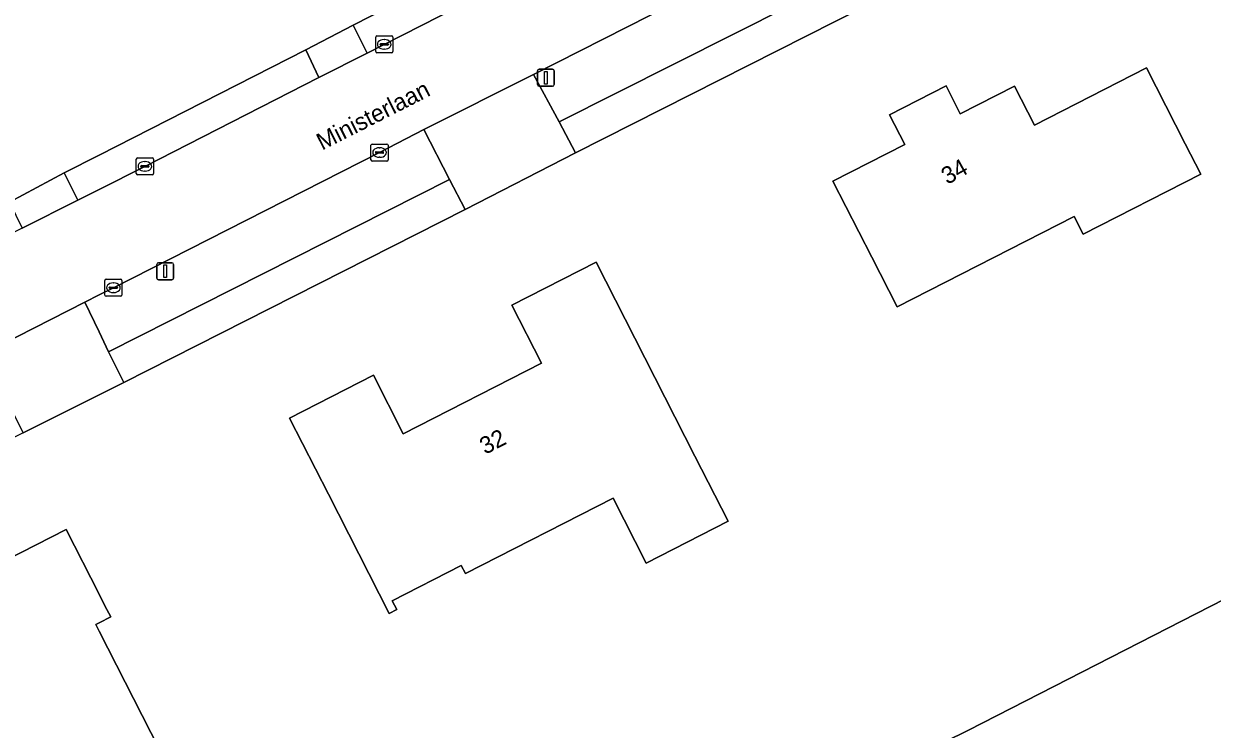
# Model space of a CAD drawing. Extents: x 162722 to 165104, y 384719 to 386284.
# Drawn here: x 163995.6 to 164065.3, y 384949.8 to 384991.2 of the extents above; entities that cross this region are included whole.
import ezdxf

# ---------------------------------------------------------------- set-up
doc = ezdxf.new("R2010")
doc.units = 0
for name, color, linetype in [('IMGEO_Erf', 7, 'Continuous'), ('IMGEO_Groenvoorziening', 7, 'Continuous'), ('IMGEO_Kolk', 7, 'Continuous'), ('IMGEO_Lichtmast', 7, 'Continuous'), ('IMGEO_Openbare_ruimte_label', 7, 'Continuous'), ('IMGEO_Pand', 7, 'Continuous'), ('IMGEO_Pand_nummerreeks', 7, 'Continuous'), ('IMGEO_Parkeervlak_open', 7, 'Continuous'), ('IMGEO_Rijbaan_lokaal_open', 7, 'Continuous'), ('IMGEO_Voetpad_open', 7, 'Continuous')]:
    doc.layers.add(name, color=color, linetype=linetype)

msp = doc.modelspace()

# ---------------------------------------------------------------- linework, layer by layer
at = {"layer": 'IMGEO_Erf'}
for points in [[(164105.943, 385023.18), (164100.563, 385020.442), (164096.277, 385018.243), (164085.388, 385012.719), (164080.225, 385010.11), (164060.269, 385000), (164056.001, 384997.838), (164051.623, 384995.596), (164027.937, 384983.596), (164021.461, 384980.283), (164001.447, 384970.146), (164000, 384969.419), (163995.555, 384967.187), (163991.381, 384965.08), (163982.898, 384961.628)], [(164162.179, 385013.171), (164145.217, 385006.018), (164139.932, 385003.079), (164135.488, 385001.967), (164135.303, 385000), (164134.643, 384992.974), (164080.212, 384964.716), (164050.974, 384949.76), (164021.235, 384935.114), (164000, 384925.382), (163995.382, 384923.265), (163988.039, 384927.89), (163958.544, 384912.864), (163932.377, 384900.522), (163925.711, 384900.92), (163897.985, 384886.845), (163900.677, 384881.543), (163922.602, 384892.673)], [(163986.006, 384976.275), (163994.739, 384980.712), (163997.946, 384982.427), (164000, 384983.471), (164012.117, 384989.629), (164014.89, 384991.078), (164032.397, 385000), (164033.264, 385000.442)], [(163995.382, 384923.265), (164000, 384925.382), (164021.235, 384935.114), (164050.974, 384949.76), (164080.212, 384964.716)]]:
    msp.add_lwpolyline(points, dxfattribs=at)
for points in [[(164045.304, 384977.479), (164043.032, 384981.932), (164047.241, 384984.08), (164046.348, 384985.83), (164049.665, 384987.522), (164050.499, 384985.888), (164053.685, 384987.513), (164054.85, 384985.23), (164061.417, 384988.582), (164063.689, 384984.129), (164064.6, 384982.344), (164057.712, 384978.829), (164057.181, 384979.87), (164046.79, 384974.567)], [(164011.175, 384968.055), (164016.089, 384970.562), (164017.84, 384967.13), (164025.939, 384971.263), (164024.203, 384974.665), (164029.144, 384977.187), (164031.417, 384972.734), (164034.939, 384965.832), (164036.891, 384962.008), (164032.082, 384959.553), (164030.14, 384963.358), (164021.48, 384958.939), (164021.239, 384959.412), (164017.189, 384957.345), (164017.452, 384956.831), (164017.016, 384956.609), (164013.448, 384963.602)], [(163983.545, 384951.385), (163992.966, 384956.185), (163991.861, 384958.354), (163998.073, 384961.519), (164000, 384957.739), (164000.347, 384957.058), (164000.684, 384956.398), (164000, 384956.048), (163999.809, 384955.95), (164000, 384955.576), (164003.541, 384948.634), (164000, 384946.829), (163997.388, 384945.497), (163996.23, 384947.769), (163987.622, 384943.383), (163985.815, 384946.93)]]:
    msp.add_lwpolyline(points, close=True, dxfattribs=at)
at = {"layer": 'IMGEO_Groenvoorziening'}
for points in [[(164026.982, 384985.419), (164050.725, 384997.366), (164049.366, 385000), (164049.239, 385000.247), (164048.752, 385000), (164025.477, 384988.187)], [(164000.553, 384971.928), (164020.558, 384982.045), (164019.048, 384984.967), (164016.445, 384983.616), (164000.843, 384975.693), (164000, 384975.271), (163999.171, 384974.857), (164000, 384973.1)]]:
    msp.add_lwpolyline(points, close=True, dxfattribs=at)
at = {"layer": 'IMGEO_Kolk'}
for p, q in [((164016.221, 384989.53), (164016.221, 384990.382)), ((164016.296, 384990.456), (164017.148, 384990.456)), ((164017.222, 384990.382), (164017.222, 384989.53)), ((164016.48, 384989.95), (164016.48, 384989.962)), ((164016.918, 384989.913), (164016.52, 384989.913)), ((164016.523, 384989.999), (164016.921, 384989.999)), ((164016.732, 384989.676), (164016.707, 384989.676)), ((164016.709, 384990.236), (164016.734, 384990.236)), ((164016.964, 384989.962), (164016.964, 384989.95)), ((164017.148, 384989.456), (164016.296, 384989.456)), ((164016.019, 384984.116), (164016.871, 384984.116)), ((164015.944, 384983.19), (164015.944, 384984.042)), ((164016.203, 384983.61), (164016.203, 384983.622)), ((164016.641, 384983.573), (164016.243, 384983.573)), ((164016.246, 384983.659), (164016.644, 384983.659)), ((164016.432, 384983.896), (164016.457, 384983.896)), ((164016.687, 384983.622), (164016.687, 384983.61)), ((164016.945, 384984.042), (164016.945, 384983.19)), ((164002.184, 384982.38), (164002.184, 384983.232)), ((164002.259, 384983.306), (164003.111, 384983.306)), ((164002.443, 384982.8), (164002.443, 384982.812)), ((164002.881, 384982.763), (164002.483, 384982.763)), ((164002.486, 384982.849), (164002.884, 384982.849)), ((164002.672, 384983.086), (164002.697, 384983.086)), ((164002.927, 384982.812), (164002.927, 384982.8)), ((164003.185, 384983.232), (164003.185, 384982.38)), ((164016.871, 384983.116), (164016.019, 384983.116)), ((164016.455, 384983.336), (164016.43, 384983.336)), ((164003.111, 384982.306), (164002.259, 384982.306)), ((164002.695, 384982.526), (164002.67, 384982.526)), ((164000.342, 384975.267), (164000.342, 384976.119)), ((164000.417, 384976.193), (164001.269, 384976.193)), ((164000.601, 384975.687), (164000.601, 384975.699)), ((164000.644, 384975.736), (164001.042, 384975.736)), ((164000.83, 384975.973), (164000.855, 384975.973)), ((164001.085, 384975.699), (164001.085, 384975.687)), ((164001.343, 384976.119), (164001.343, 384975.267)), ((164001.269, 384975.193), (164000.417, 384975.193)), ((164001.039, 384975.65), (164000.641, 384975.65)), ((164000.853, 384975.413), (164000.828, 384975.413))]:
    msp.add_line(p, q, dxfattribs=at)
for points in [[(164016.221, 384989.53), (164016.221, 384990.382)], [(164016.296, 384990.456), (164017.148, 384990.456)], [(164017.222, 384990.382), (164017.222, 384989.53)], [(164017.148, 384989.456), (164016.296, 384989.456)], [(164016.019, 384984.116), (164016.871, 384984.116)], [(164015.944, 384983.19), (164015.944, 384984.042)], [(164016.945, 384984.042), (164016.945, 384983.19)], [(164002.184, 384982.38), (164002.184, 384983.232)], [(164002.259, 384983.306), (164003.111, 384983.306)], [(164003.185, 384983.232), (164003.185, 384982.38)], [(164016.871, 384983.116), (164016.019, 384983.116)], [(164003.111, 384982.306), (164002.259, 384982.306)], [(164000.342, 384975.267), (164000.342, 384976.119)], [(164000.417, 384976.193), (164001.269, 384976.193)], [(164001.343, 384976.119), (164001.343, 384975.267)], [(164001.269, 384975.193), (164000.417, 384975.193)]]:
    msp.add_lwpolyline(points, dxfattribs=at)
for centre, radius, start, end in [((164016.298, 384990.38), 0.0765, 91.55205, 178.44795), ((164016.298, 384990.38), 0.0765, 91.55205, 178.44795), ((164017.146, 384990.38), 0.0765, 1.55205, 88.44795), ((164017.146, 384990.38), 0.0765, 1.55205, 88.44795), ((164016.52, 384989.959), 0.0403, 85.87752, 175.75265), ((164016.517, 384989.949), 0.0366, 178.93798, 274.71019), ((164016.921, 384989.956), 0.043, 264.86636, 352.45326), ((164016.925, 384989.961), 0.0386, 1.73085, 96.63898), ((164016.298, 384989.532), 0.0765, 181.55205, 268.44795), ((164016.298, 384989.532), 0.0765, 181.55205, 268.44795), ((164017.146, 384989.532), 0.0765, 271.55205, 358.44795), ((164017.146, 384989.532), 0.0765, 271.55205, 358.44795), ((164016.021, 384984.04), 0.0765, 91.55205, 178.44795), ((164016.021, 384984.04), 0.0765, 91.55205, 178.44795), ((164016.869, 384984.04), 0.0765, 1.55205, 88.44795), ((164016.869, 384984.04), 0.0765, 1.55205, 88.44795), ((164016.243, 384983.619), 0.0403, 85.87752, 175.75265), ((164016.24, 384983.609), 0.0366, 178.93798, 274.71019), ((164016.644, 384983.616), 0.043, 264.86636, 352.45326), ((164016.648, 384983.621), 0.0386, 1.73085, 96.63898), ((164002.261, 384983.23), 0.0765, 91.55205, 178.44795), ((164002.261, 384983.23), 0.0765, 91.55205, 178.44795), ((164002.483, 384982.809), 0.0403, 85.87752, 175.75265), ((164002.48, 384982.799), 0.0366, 178.93798, 274.71019), ((164002.884, 384982.806), 0.043, 264.86636, 352.45326), ((164002.888, 384982.811), 0.0386, 1.73085, 96.63898), ((164003.109, 384983.23), 0.0765, 1.55205, 88.44795), ((164003.109, 384983.23), 0.0765, 1.55205, 88.44795), ((164016.021, 384983.192), 0.0765, 181.55205, 268.44795), ((164016.021, 384983.192), 0.0765, 181.55205, 268.44795), ((164016.869, 384983.192), 0.0765, 271.55205, 358.44795), ((164016.869, 384983.192), 0.0765, 271.55205, 358.44795), ((164002.261, 384982.382), 0.0765, 181.55205, 268.44795), ((164002.261, 384982.382), 0.0765, 181.55205, 268.44795), ((164003.109, 384982.382), 0.0765, 271.55205, 358.44795), ((164003.109, 384982.382), 0.0765, 271.55205, 358.44795), ((164000.419, 384976.117), 0.0765, 91.55205, 178.44795), ((164000.419, 384976.117), 0.0765, 91.55205, 178.44795), ((164000.641, 384975.696), 0.0403, 85.87752, 175.75265), ((164001.046, 384975.698), 0.0386, 1.73085, 96.63898), ((164001.267, 384976.117), 0.0765, 1.55205, 88.44795), ((164001.267, 384976.117), 0.0765, 1.55205, 88.44795), ((164000.419, 384975.269), 0.0765, 181.55205, 268.44795), ((164000.419, 384975.269), 0.0765, 181.55205, 268.44795), ((164000.638, 384975.686), 0.0366, 178.93798, 274.71019), ((164001.042, 384975.693), 0.043, 264.86636, 352.45326), ((164001.267, 384975.269), 0.0765, 271.55205, 358.44795), ((164001.267, 384975.269), 0.0765, 271.55205, 358.44795)]:
    msp.add_arc(centre, radius, start, end, dxfattribs=at)
for centre, major_axis, ratio, start_param, end_param in [((164016.708, 384989.956), (-0.387, 0.002), 0.722429, 4.712389, 7.853982), ((164016.733, 384989.956), (-0.39, 0.002), 0.717154, 1.570796, 4.712389), ((164016.431, 384983.616), (-0.387, 0.002), 0.722429, 4.712389, 7.853982), ((164016.456, 384983.616), (-0.39, 0.002), 0.717154, 1.570796, 4.712389), ((164002.671, 384982.806), (-0.387, 0.002), 0.722429, 4.712389, 7.853982), ((164002.696, 384982.806), (-0.39, 0.002), 0.717154, 1.570796, 4.712389), ((164000.829, 384975.693), (-0.387, 0.002), 0.722429, 4.712389, 7.853982), ((164000.854, 384975.693), (-0.39, 0.002), 0.717154, 1.570796, 4.712389)]:
    msp.add_ellipse(centre, major_axis=major_axis, ratio=ratio, start_param=start_param, end_param=end_param, dxfattribs=at)
at = {"layer": 'IMGEO_Lichtmast'}
for p, q in [((164025.699, 384987.599), (164025.699, 384988.399)), ((164025.699, 384988.399), (164025.699, 384987.599)), ((164025.799, 384988.499), (164026.589, 384988.499)), ((164026.589, 384988.499), (164025.799, 384988.499)), ((164026.689, 384988.399), (164026.689, 384987.599)), ((164026.689, 384987.599), (164026.689, 384988.399)), ((164026.589, 384987.499), (164025.799, 384987.499)), ((164025.799, 384987.499), (164026.589, 384987.499)), ((164003.478, 384977.161), (164004.268, 384977.161)), ((164004.268, 384977.161), (164003.478, 384977.161)), ((164003.378, 384976.261), (164003.378, 384977.061)), ((164003.378, 384977.061), (164003.378, 384976.261)), ((164004.368, 384977.061), (164004.368, 384976.261)), ((164004.368, 384976.261), (164004.368, 384977.061)), ((164004.268, 384976.161), (164003.478, 384976.161)), ((164003.478, 384976.161), (164004.268, 384976.161))]:
    msp.add_line(p, q, dxfattribs=at)
for points in [[(164026.119, 384988.374), (164026.269, 384988.374), (164026.269, 384987.624), (164026.119, 384987.624), (164026.119, 384988.374)], [(164003.798, 384977.036), (164003.948, 384977.036), (164003.948, 384976.286), (164003.798, 384976.286), (164003.798, 384977.036)]]:
    msp.add_lwpolyline(points, dxfattribs=at)
for centre, start, end in [((164025.799, 384988.399), 90, 180), ((164025.799, 384988.399), 90, 180), ((164026.589, 384988.399), 0, 90), ((164026.589, 384988.399), 360, 90), ((164025.799, 384987.599), 180, 270), ((164025.799, 384987.599), 180, 270), ((164026.589, 384987.599), 270, 0), ((164026.589, 384987.599), 270, 0), ((164003.478, 384977.061), 90, 180), ((164003.478, 384977.061), 90, 180), ((164004.268, 384977.061), 0, 90), ((164004.268, 384977.061), 360, 90), ((164003.478, 384976.261), 180, 270), ((164003.478, 384976.261), 180, 270), ((164004.268, 384976.261), 270, 0), ((164004.268, 384976.261), 270, 0)]:
    msp.add_arc(centre, 0.1, start, end, dxfattribs=at)
at = {"layer": 'IMGEO_Pand'}
for points in [[(164045.304, 384977.479), (164046.79, 384974.567), (164057.181, 384979.87), (164057.712, 384978.829), (164064.6, 384982.344), (164063.689, 384984.129), (164061.417, 384988.582), (164054.85, 384985.23), (164053.685, 384987.513), (164050.499, 384985.888), (164049.665, 384987.522), (164046.348, 384985.83), (164047.241, 384984.08), (164043.032, 384981.932)], [(164017.016, 384956.609), (164017.452, 384956.831), (164017.189, 384957.345), (164021.239, 384959.412), (164021.48, 384958.939), (164030.14, 384963.358), (164032.082, 384959.553), (164036.891, 384962.008), (164034.939, 384965.832), (164031.417, 384972.734), (164029.144, 384977.187), (164024.203, 384974.665), (164025.939, 384971.263), (164017.84, 384967.13), (164016.089, 384970.562), (164011.175, 384968.055), (164013.448, 384963.602)], [(164000.347, 384957.058), (164000, 384957.739), (163998.073, 384961.519), (163991.861, 384958.354), (163992.966, 384956.185), (163983.545, 384951.385), (163985.815, 384946.93), (163987.622, 384943.383), (163996.23, 384947.769), (163997.388, 384945.497), (164000, 384946.829), (164003.541, 384948.634), (164000, 384955.576), (163999.809, 384955.95), (164000, 384956.048), (164000.684, 384956.398)]]:
    msp.add_lwpolyline(points, close=True, dxfattribs=at)
at = {"layer": 'IMGEO_Parkeervlak_open'}
msp.add_lwpolyline([(164033.264, 385000.442), (164032.397, 385000), (164014.89, 384991.078), (164015.73, 384989.449), (164016.722, 384989.956), (164031.839, 384997.657)], dxfattribs=at)
msp.add_lwpolyline([(164012.117, 384989.629), (164000, 384983.471), (163997.946, 384982.427), (163998.758, 384980.82), (164000, 384981.448), (164002.685, 384982.806), (164012.885, 384988.012)], close=True, dxfattribs=at)
at = {"layer": 'IMGEO_Rijbaan_lokaal_open'}
for points in [[(164101.609, 385033.009), (164096.471, 385030.405), (164088.372, 385026.349), (164082.061, 385023.117), (164081.011, 385022.579), (164066.906, 385015.461), (164065.538, 385014.795), (164058.234, 385011.087), (164052.18, 385007.948), (164046.901, 385005.343), (164046.648, 385005.238), (164034.319, 384998.907), (164034.19, 384998.857), (164031.839, 384997.657), (164016.722, 384989.956), (164015.73, 384989.449), (164012.885, 384988.012), (164002.685, 384982.806), (164000, 384981.448), (163998.758, 384980.82), (163995.493, 384979.191), (163988.741, 384975.747), (163986.456, 384974.572)], [(163989.052, 384969.703), (163993.208, 384971.822), (163999.171, 384974.857), (164000, 384975.271), (164000.843, 384975.693), (164016.445, 384983.616), (164019.048, 384984.967), (164025.477, 384988.187), (164048.752, 385000), (164049.239, 385000.247), (164053.614, 385002.474), (164054.784, 385003.095), (164069.482, 385010.558), (164077.864, 385014.778), (164083.036, 385017.376), (164084.605, 385018.186), (164093.91, 385022.896), (164098.211, 385025.06), (164100.766, 385026.367), (164104.574, 385028.285)]]:
    msp.add_lwpolyline(points, dxfattribs=at)
at = {"layer": 'IMGEO_Voetpad_open'}
for points in [[(164026.982, 384985.419), (164027.937, 384983.596), (164051.623, 384995.596), (164050.725, 384997.366)], [(164015.73, 384989.449), (164014.89, 384991.078), (164012.117, 384989.629), (164012.885, 384988.012)], [(164020.558, 384982.045), (164021.461, 384980.283), (164027.937, 384983.596), (164026.982, 384985.419), (164025.477, 384988.187), (164019.048, 384984.967)], [(163998.758, 384980.82), (163997.946, 384982.427), (163994.739, 384980.712), (163995.493, 384979.191)], [(164000.553, 384971.928), (164001.447, 384970.146), (164021.461, 384980.283), (164020.558, 384982.045)], [(163994.661, 384968.927), (163995.555, 384967.187), (164000, 384969.419), (164001.447, 384970.146), (164000.553, 384971.928), (164000, 384973.1), (163999.171, 384974.857), (163993.208, 384971.822)]]:
    msp.add_lwpolyline(points, close=True, dxfattribs=at)

# ---------------------------------------------------------------- texts
at = {"layer": 'IMGEO_Openbare_ruimte_label'}
msp.add_text('Ministerlaan', height=1, rotation=26.92363, dxfattribs=at).set_placement((164013.077, 384983.723))
at = {"layer": 'IMGEO_Pand_nummerreeks'}
for s, rotation, p in [('34', 29.02772, (164049.739, 384981.714)), ('32', 27.03567, (164022.642, 384965.897))]:
    msp.add_text(s, height=1, rotation=rotation, dxfattribs=at).set_placement(p)

doc.saveas('drawing.dxf')
